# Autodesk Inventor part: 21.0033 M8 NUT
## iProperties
Created: 2012-10
Part Number: 21.0033 M8 NUT
Document SubType Name: Modeling
Designer: Administrator
Density: 7.85 g/cm^3
Material: Steel
Mass: 3.55938 g
Surface Area: 5.45864 cm^2
Volume: 0.453424 cm^3
Author: Administrator
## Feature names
1. Base1
